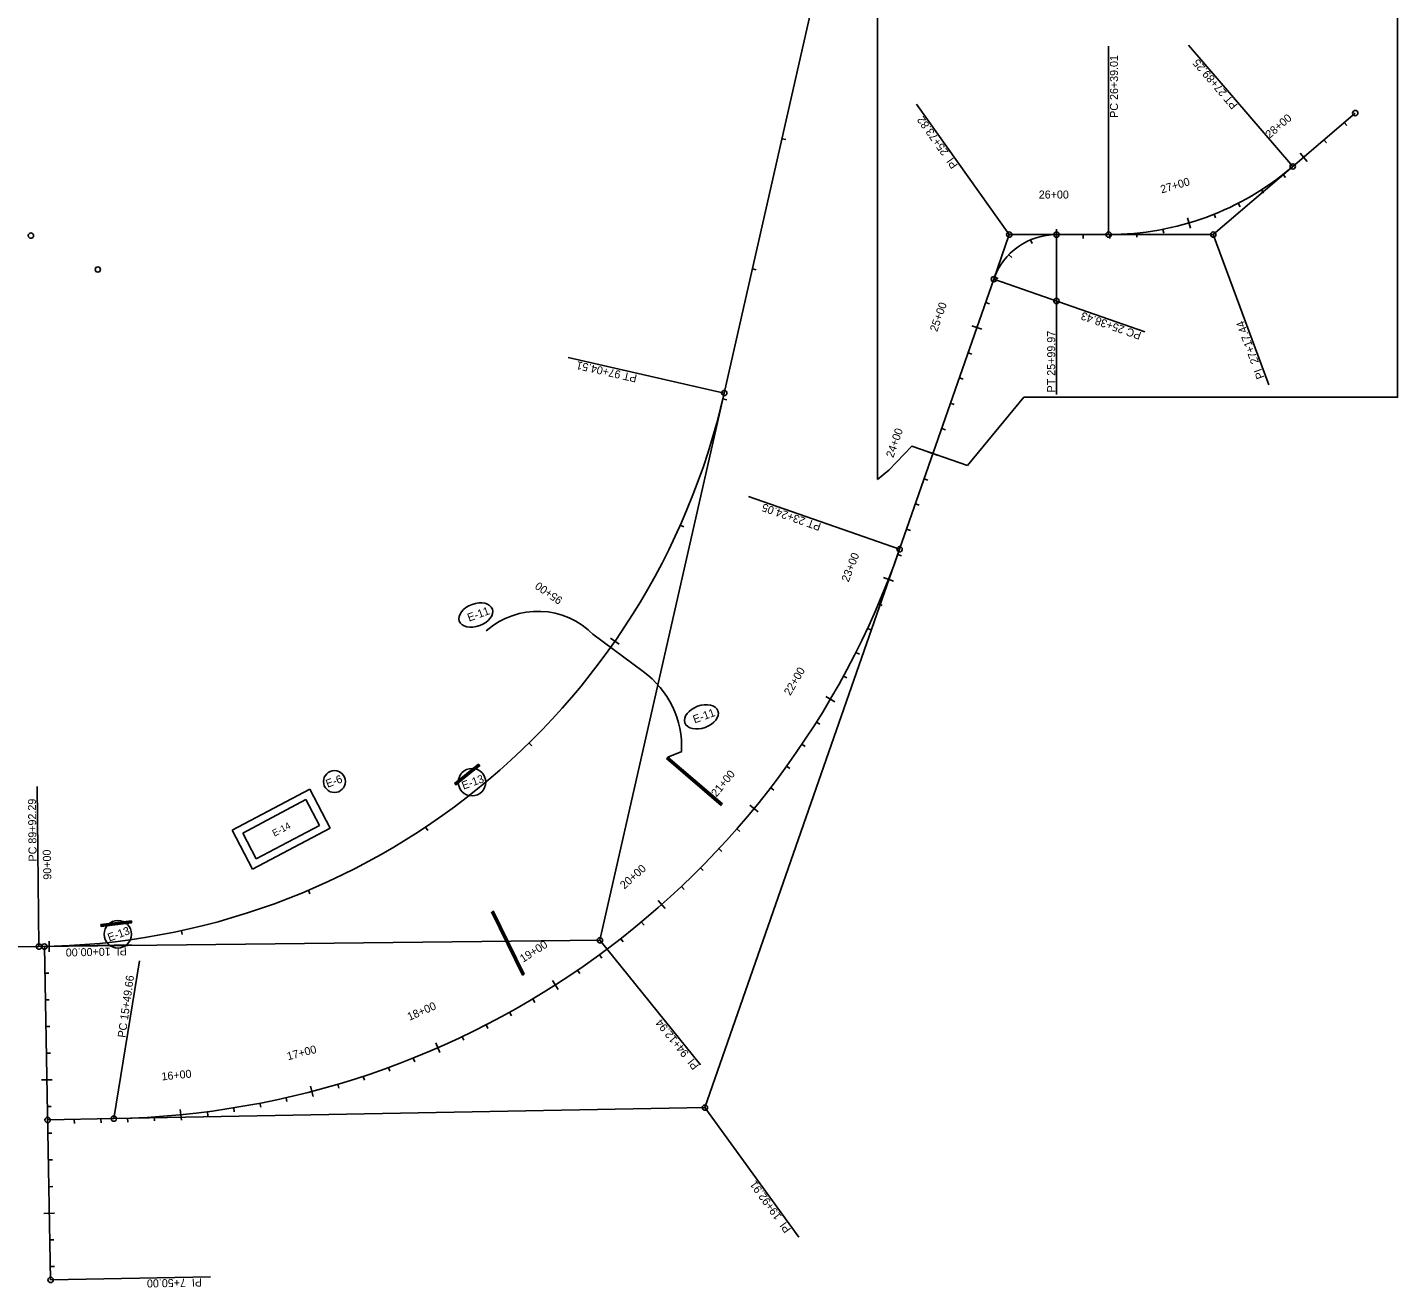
# Model space of a CAD drawing. Extents: x 1710760 to 1713003, y 548603 to 551142.
# Drawn here: x 1711724 to 1712752, y 548957 to 549901 of the extents above; entities that cross this region are included whole.
import ezdxf

# ---------------------------------------------------------------- set-up
doc = ezdxf.new("R2010")
doc.units = 0
for name, color, linetype in [('R_Erosion', 7, 'Continuous'), ('R_Erosion_STG 2', 7, 'Continuous'), ('R_Horz Alg', 7, 'Continuous'), ('R_Horz Alg Annot', 7, 'Continuous'), ('R_No Plot', 7, 'Continuous')]:
    doc.layers.add(name, color=color, linetype=linetype)

msp = doc.modelspace()

# ---------------------------------------------------------------- linework, layer by layer
at = {"layer": 'R_Erosion'}
for p, q in [((1712148.3, 549446.5), (1712186.1, 549418.7)), ((1712214.9, 549358.7), (1712204.5, 549354.4)), ((1712044.6, 549334.7), (1712062.6, 549349.2)), ((1712060.3, 549345.4), (1712060.5, 549347.5)), ((1712061.4, 549346.3), (1712061.6, 549348.4)), ((1712062.5, 549347.1), (1712062.7, 549349)), ((1712204.5, 549354.4), (1712203.5, 549353.3)), ((1712203.5, 549353.3), (1712244.6, 549318.1)), ((1712205.8, 549353.3), (1712203.6, 549353.2)), ((1712204.7, 549354.3), (1712204.4, 549354.2)), ((1712245.6, 549319.3), (1712204.5, 549354.4)), ((1712206.8, 549352.4), (1712204.7, 549352.3)), ((1712207.9, 549351.5), (1712205.8, 549351.3)), ((1712209, 549350.6), (1712206.9, 549350.4)), ((1712210.1, 549349.7), (1712207.9, 549349.5)), ((1712211.1, 549348.7), (1712209, 549348.6)), ((1712212.2, 549347.8), (1712210.1, 549347.7)), ((1712213.3, 549346.9), (1712211.2, 549346.7)), ((1712047, 549334.7), (1712047.2, 549336.9)), ((1712048.1, 549335.6), (1712048.4, 549337.7)), ((1712049.2, 549336.5), (1712049.5, 549338.6)), ((1712050.3, 549337.4), (1712050.6, 549339.5)), ((1712051.4, 549338.3), (1712051.7, 549340.4)), ((1712052.5, 549339.2), (1712052.8, 549341.3)), ((1712053.6, 549340.1), (1712053.9, 549342.2)), ((1712054.7, 549340.9), (1712055, 549343.1)), ((1712055.8, 549341.8), (1712056.1, 549343.9)), ((1712056.9, 549342.7), (1712057.2, 549344.8)), ((1712058, 549343.6), (1712058.3, 549345.7)), ((1712059.1, 549344.5), (1712059.4, 549346.6)), ((1712214.4, 549346), (1712212.2, 549345.8)), ((1712215.4, 549345.1), (1712213.3, 549344.9)), ((1712216.5, 549344.1), (1712214.4, 549344)), ((1712217.6, 549343.2), (1712215.5, 549343.1)), ((1712218.7, 549342.3), (1712216.5, 549342.1)), ((1712219.7, 549341.4), (1712217.6, 549341.2)), ((1712220.8, 549340.5), (1712218.7, 549340.3)), ((1712221.9, 549339.6), (1712219.8, 549339.4)), ((1712223, 549338.6), (1712220.8, 549338.5)), ((1712224, 549337.7), (1712221.9, 549337.5)), ((1712225.1, 549336.8), (1712223, 549336.6)), ((1711877.8, 549299.6), (1711936.1, 549330.4)), ((1711936.1, 549330.4), (1711951.4, 549301.2)), ((1712045, 549334.3), (1712045, 549335.1)), ((1712045.9, 549333.9), (1712046.1, 549336)), ((1712226.2, 549335.9), (1712224.1, 549335.7)), ((1712227.3, 549335), (1712225.1, 549334.8)), ((1712228.3, 549334), (1712226.2, 549333.9)), ((1712229.4, 549333.1), (1712227.3, 549333)), ((1712230.5, 549332.2), (1712228.4, 549332)), ((1712231.6, 549331.3), (1712229.4, 549331.1)), ((1712232.6, 549330.4), (1712230.5, 549330.2)), ((1712233.7, 549329.4), (1712231.6, 549329.3)), ((1712234.8, 549328.5), (1712232.7, 549328.4)), ((1712235.9, 549327.6), (1712233.7, 549327.4)), ((1712236.9, 549326.7), (1712234.8, 549326.5)), ((1711885.8, 549297.5), (1711933.2, 549322.6)), ((1711933.2, 549322.6), (1711943.4, 549303.2)), ((1712238, 549325.8), (1712235.9, 549325.6)), ((1712239.1, 549324.8), (1712237, 549324.7)), ((1712240.2, 549323.9), (1712238, 549323.8)), ((1712241.2, 549323), (1712239.1, 549322.8)), ((1712242.3, 549322.1), (1712240.2, 549321.9)), ((1712243.4, 549321.2), (1712241.3, 549321)), ((1712244.5, 549320.3), (1712242.3, 549320.1)), ((1712245.5, 549319.3), (1712243.4, 549319.2)), ((1712244.8, 549318.3), (1712244.5, 549318.2)), ((1711877.8, 549299.6), (1711893.1, 549270.3)), ((1711885.8, 549297.5), (1711896, 549278.2)), ((1711893.1, 549270.3), (1711951.4, 549301.2)), ((1711896, 549278.2), (1711943.4, 549303.2)), ((1712095.6, 549191), (1712072.2, 549238.5)), ((1712074.6, 549237), (1712072.6, 549237.7)), ((1712074, 549238.3), (1712072.7, 549238.7)), ((1712075.2, 549235.8), (1712073.2, 549236.4)), ((1712073.5, 549239.2), (1712096.9, 549191.7)), ((1712075.9, 549234.5), (1712073.8, 549235.2)), ((1712076.5, 549233.2), (1712074.5, 549233.9)), ((1711802.3, 549231.7), (1711779.5, 549228.9)), ((1711779.6, 549228.1), (1711780.2, 549229)), ((1711780.3, 549227.5), (1711781.6, 549229.1)), ((1711781.7, 549227.6), (1711783, 549229.3)), ((1711783.1, 549227.8), (1711784.4, 549229.5)), ((1711784.5, 549228), (1711785.8, 549229.7)), ((1711785.9, 549228.2), (1711787.2, 549229.8)), ((1711787.3, 549228.3), (1711788.6, 549230)), ((1711788.7, 549228.5), (1711790, 549230.2)), ((1711790.1, 549228.7), (1711791.4, 549230.3)), ((1711791.5, 549228.8), (1711792.8, 549230.5)), ((1711792.9, 549229), (1711794.2, 549230.7)), ((1711794.3, 549229.2), (1711795.7, 549230.9)), ((1711795.8, 549229.4), (1711797.1, 549231)), ((1711797.2, 549229.5), (1711798.5, 549231.2)), ((1711798.6, 549229.7), (1711799.9, 549231.4)), ((1711800, 549229.9), (1711801.3, 549231.6)), ((1711801.4, 549230.1), (1711802.3, 549231.3)), ((1712077.1, 549232), (1712075.1, 549232.6)), ((1712077.7, 549230.7), (1712075.7, 549231.4)), ((1712078.3, 549229.4), (1712076.3, 549230.1)), ((1712079, 549228.2), (1712077, 549228.8)), ((1712079.6, 549226.9), (1712077.6, 549227.6)), ((1712080.2, 549225.6), (1712078.2, 549226.3)), ((1712080.8, 549224.3), (1712078.8, 549225)), ((1712081.5, 549223.1), (1712079.5, 549223.8)), ((1712082.1, 549221.8), (1712080.1, 549222.5)), ((1712082.7, 549220.5), (1712080.7, 549221.2)), ((1712083.3, 549219.3), (1712081.3, 549220)), ((1712084, 549218), (1712082, 549218.7)), ((1712084.6, 549216.7), (1712082.6, 549217.4)), ((1712085.2, 549215.5), (1712083.2, 549216.1)), ((1712085.8, 549214.2), (1712083.8, 549214.9)), ((1712086.5, 549212.9), (1712084.5, 549213.6)), ((1712087.1, 549211.7), (1712085.1, 549212.3)), ((1712087.7, 549210.4), (1712085.7, 549211.1)), ((1712088.3, 549209.1), (1712086.3, 549209.8)), ((1712089, 549207.8), (1712087, 549208.5)), ((1712089.6, 549206.6), (1712087.6, 549207.3)), ((1712090.2, 549205.3), (1712088.2, 549206)), ((1712090.8, 549204), (1712088.8, 549204.7)), ((1712091.5, 549202.8), (1712089.5, 549203.5)), ((1712092.1, 549201.5), (1712090.1, 549202.2)), ((1712092.7, 549200.2), (1712090.7, 549200.9)), ((1712093.3, 549199), (1712091.3, 549199.6)), ((1712094, 549197.7), (1712092, 549198.4)), ((1712094.6, 549196.4), (1712092.6, 549197.1)), ((1712095.2, 549195.2), (1712093.2, 549195.8)), ((1712095.8, 549193.9), (1712093.8, 549194.6)), ((1712096.5, 549192.6), (1712094.5, 549193.3)), ((1712096.6, 549191.5), (1712095.1, 549192)), ((1712096.9, 549191.7), (1712095.6, 549191))]:
    msp.add_line(p, q, dxfattribs=at)
for points in [[(1712062.6, 549349.2), (1712063.5, 549348), (1712045.6, 549333.6), (1712044.6, 549334.7)], [(1711779.5, 549228.9), (1711779.7, 549227.4), (1711802.5, 549230.2), (1711802.3, 549231.7)]]:
    msp.add_lwpolyline(points, dxfattribs=at)
msp.add_circle((1711954.6, 549336.1), 8.26, dxfattribs=at)
for centre, radius, start, end in [((1712107.1, 549405.4), 58.3, 44.026, 131.674), ((1712143.9, 549361.5), 71, 357.7547, 53.5498)]:
    msp.add_arc(centre, radius, start, end, dxfattribs=at)
for centre in [(1712060.6, 549460.9), (1712229.7, 549384.6)]:
    msp.add_ellipse(centre, major_axis=(12.4, 4.5), ratio=0.638788, dxfattribs=at)
at = {"layer": 'R_Erosion_STG 2'}
for centre in [(1712057.7, 549335.6), (1711792.2, 549221.6)]:
    msp.add_circle(centre, 10.3, dxfattribs=at)
at = {"layer": 'R_Horz Alg'}
for p, q in [((1712246.8, 549627.3), (1712450.8, 550525.8)), ((1712673, 549797.1), (1712719.9, 549837.2)), ((1712495.9, 549746.1), (1712535, 549746.1)), ((1712378.3, 549510.2), (1712448.9, 549712.7)), ((1711391.8, 549208.5), (1711733, 549212.4)), ((1711741.8, 548962.5), (1711737.1, 549212.4)), ((1711739.5, 549082.4), (1711789.2, 549083.4))]:
    msp.add_line(p, q, dxfattribs=at)
for centre, radius, start, end in [((1712535, 549958.3), 212.2, 270, 310.5648), ((1712495.9, 549696.3), 49.8, 90, 160.7734), ((1711727, 549745.3), 533, 270.6428, 347.2066), ((1711777.2, 549719.9), 636.6, 271.0787, 340.7734)]:
    msp.add_arc(centre, radius, start, end, dxfattribs=at)
at = {"layer": 'R_Horz Alg Annot'}
for p, q in [((1712613.4, 549746.1), (1712673, 549797.1)), ((1712448.9, 549712.7), (1712460.5, 549746.1)), ((1712460.5, 549746.1), (1712495.9, 549746.1)), ((1712535, 549746.1), (1712613.4, 549746.1)), ((1712153.6, 549217.1), (1712246.8, 549627.3)), ((1712232.3, 549091.7), (1712378.3, 549510.2)), ((1711733, 549212.4), (1712153.6, 549217.1)), ((1711737.1, 549212.4), (1711802.4, 549213.6)), ((1711789.2, 549083.4), (1712232.3, 549091.7))]:
    msp.add_line(p, q, dxfattribs=at)
for points in [[(1712535, 549746.1), (1712535, 549887.4)], [(1712673, 549797.1), (1712594.9, 549888.2)], [(1712460.5, 549746.1), (1712391, 549843.9)], [(1712713.5, 549827.8), (1712711.5, 549830.1)], [(1712293, 549817.3), (1712290.1, 549817.9)], [(1712698.3, 549814.8), (1712696.3, 549817.1)], [(1712678.5, 549807.1), (1712683.7, 549801)], [(1712667.7, 549788.8), (1712665.8, 549791.2)], [(1712651.1, 549777.1), (1712649.5, 549779.6)], [(1712633.6, 549767), (1712632.2, 549769.7)], [(1712594, 549758.6), (1712596.3, 549750.9)], [(1712615.1, 549758.6), (1712614, 549761.3)], [(1712496, 549750.1), (1712496, 549742.1)], [(1712576.3, 549747.1), (1712575.7, 549750)], [(1712477.7, 549739.4), (1712476.5, 549742.1)], [(1712495.9, 549746.1), (1712495.9, 549626.1)], [(1712516, 549743.1), (1712516, 549746.1)], [(1712536, 549743.1), (1712536, 549746.1)], [(1712556.2, 549744.1), (1712555.9, 549747.1)], [(1712613.4, 549746.1), (1712655, 549633.5)], [(1712462.3, 549728.8), (1712460.1, 549730.9)], [(1712270.8, 549719.7), (1712267.9, 549720.4)], [(1712448.9, 549712.7), (1712562.2, 549673.1)], [(1712452.2, 549713.1), (1712449.4, 549714.1)], [(1712445.6, 549694.3), (1712442.8, 549695.3)], [(1712432.4, 549677.7), (1712440, 549675.1)], [(1712432.5, 549656.5), (1712429.6, 549657.5)], [(1712246.8, 549627.3), (1712129.8, 549653.9)], [(1712425.9, 549637.6), (1712423.1, 549638.6)], [(1712248.7, 549622.2), (1712245.8, 549622.9)], [(1712419.3, 549618.7), (1712416.5, 549619.7)], [(1712412.7, 549599.8), (1712409.9, 549600.8)], [(1712399.5, 549583.3), (1712407.1, 549580.6)], [(1712399.5, 549562.1), (1712396.7, 549563.1)], [(1712378.3, 549510.2), (1712265, 549549.8)], [(1712393, 549543.2), (1712390.1, 549544.2)], [(1712216.6, 549527.1), (1712213.8, 549528.3)], [(1712386.4, 549524.3), (1712383.5, 549525.3)], [(1712379.8, 549505.4), (1712376.9, 549506.4)], [(1712366.2, 549489.1), (1712373.7, 549486.2)], [(1712365.1, 549468), (1712362.4, 549469.2)], [(1712356.9, 549449.7), (1712354.2, 549450.9)], [(1712161.5, 549443.6), (1712168.1, 549439)], [(1712348.1, 549431.6), (1712345.5, 549432.9)], [(1712338.8, 549413.8), (1712336.2, 549415.2)], [(1712322.9, 549399.8), (1712329.8, 549395.8)], [(1712318.5, 549379.1), (1712315.9, 549380.7)], [(1712102.5, 549362.8), (1712100.4, 549365)], [(1712307.5, 549362.3), (1712305, 549364)], [(1712296, 549345.8), (1712293.6, 549347.6)], [(1711733, 549212.4), (1711731.7, 549332.3)], [(1712284, 549329.7), (1712281.6, 549331.5)], [(1712266.1, 549318.4), (1712272.3, 549313.3)], [(1712024.6, 549299.5), (1712022.9, 549302)], [(1712258.5, 549298.6), (1712256.2, 549300.6)], [(1712245, 549283.7), (1712242.8, 549285.8)], [(1712231.1, 549269.3), (1712229, 549271.4)], [(1711936.2, 549251.8), (1711935, 549254.6)], [(1712216.7, 549255.2), (1712214.7, 549257.4)], [(1712197.3, 549246.9), (1712202.6, 549240.9)], [(1711840.5, 549221.5), (1711839.8, 549224.4)], [(1712186.7, 549228.5), (1712184.8, 549230.8)], [(1711740.6, 549216.5), (1711740.8, 549208.5)], [(1712153.6, 549217.1), (1712229, 549123.7)], [(1712171, 549215.9), (1712169.2, 549218.3)], [(1712155, 549203.8), (1712153.2, 549206.2)], [(1711789.2, 549083.4), (1711808.5, 549201.7)], [(1712138.6, 549192.2), (1712136.9, 549194.7)], [(1711740.4, 549192.5), (1711737.4, 549192.4)], [(1712118.1, 549187), (1712122.4, 549180.2)], [(1711740.8, 549172.5), (1711737.8, 549172.4)], [(1712104.8, 549170.5), (1712103.2, 549173.1)], [(1712087.4, 549160.5), (1712085.9, 549163.1)], [(1711741.2, 549152.5), (1711738.2, 549152.4)], [(1712069.6, 549151), (1712068.3, 549153.7)], [(1712051.6, 549142.1), (1712050.3, 549144.8)], [(1711741.6, 549132.5), (1711738.6, 549132.4)], [(1712030.5, 549140.2), (1712033.7, 549132.9)], [(1711996, 549118.9), (1711995, 549121.7)], [(1712014.8, 549126), (1712013.7, 549128.8)], [(1711734.9, 549112.4), (1711742.9, 549112.5)], [(1711977, 549112.3), (1711976.1, 549115.1)], [(1711936.7, 549107.7), (1711938.7, 549100)], [(1711957.9, 549106.3), (1711957, 549109.2)], [(1711742.3, 549092.5), (1711739.3, 549092.4)], [(1711839, 549090.3), (1711839.8, 549082.3)], [(1711879.5, 549088.5), (1711879.1, 549091.5)], [(1711899.3, 549092), (1711898.7, 549095)], [(1711919, 549096.2), (1711918.3, 549099.1)], [(1712232.3, 549091.7), (1712302.7, 548994.5)], [(1711759.6, 549079.8), (1711759.5, 549082.8)], [(1711779.6, 549080.2), (1711779.5, 549083.2)], [(1711799.6, 549080.7), (1711799.5, 549083.7)], [(1711819.7, 549081.7), (1711819.5, 549084.7)], [(1711859.7, 549085.6), (1711859.3, 549088.6)], [(1711742.7, 549072.5), (1711739.7, 549072.4)], [(1711743.1, 549052.5), (1711740.1, 549052.4)], [(1711743.4, 549032.5), (1711740.4, 549032.4)], [(1711736.8, 549012.4), (1711744.8, 549012.5)], [(1711744.2, 548992.5), (1711741.2, 548992.5)], [(1711744.6, 548972.5), (1711741.6, 548972.5)], [(1711741.8, 548962.5), (1711861.7, 548964.7)]]:
    msp.add_lwpolyline(points, dxfattribs=at)
for centre in [(1712719.9, 549837.2), (1712673, 549797.1), (1712460.5, 549746.1), (1712495.9, 549746.1), (1712535, 549746.1), (1712613.4, 549746.1), (1711727, 549745.3), (1711777.2, 549719.9), (1712448.9, 549712.7), (1712495.9, 549696.3), (1712246.8, 549627.3), (1712378.3, 549510.2), (1711733, 549212.4), (1711733, 549212.4), (1711737.1, 549212.4), (1712153.6, 549217.1), (1712232.3, 549091.7), (1711739.5, 549082.4), (1711789.2, 549083.4), (1711741.8, 548962.5)]:
    msp.add_circle(centre, 2, dxfattribs=at)
at = {"layer": 'R_No Plot'}
msp.add_line((1712429.3, 549572.9), (1712471.5, 549624.2), dxfattribs=at)
for points in [[(1712635.8, 549942.6), (1712361.6, 549942.6), (1712361.6, 549562.6)], [(1712471.5, 549624.2), (1712751.6, 549624.2), (1712751.6, 549942.6), (1712636.3, 549942.6)], [(1712361.6, 549562.6), (1712370.3, 549569.5), (1712387.4, 549587.5), (1712429.3, 549572.9)]]:
    msp.add_lwpolyline(points, dxfattribs=at)

# ---------------------------------------------------------------- texts
at = {"layer": 'R_Erosion'}
for s, height, rotation, p in [('E-11', 6, 20, (1712055.5, 549455.9)), ('E-11', 6, 20, (1712224.6, 549379.6)), ('E-6 ', 6, 20, (1711949.4, 549331.4)), ('E-14', 5.08, 27.831, (1711909.6, 549294.7))]:
    msp.add_text(s, height=height, rotation=rotation, dxfattribs=at).set_placement(p)
at = {"layer": 'R_Erosion_STG 2'}
for p in [(1712051.3, 549330), (1711785.8, 549216.1)]:
    msp.add_text('E-13', height=6, rotation=20, dxfattribs=at).set_placement(p)
at = {"layer": 'R_Horz Alg Annot'}
for s, rotation, p in [('PC 26+39.01', 90, (1712542, 549833.6)), ('PT 27+89.25', 130.5648, (1712632.1, 549843.3)), ('PI  25+73.82', 125.3867, (1712422.3, 549798.2)), ('28+00', 40.5648, (1712655.7, 549817.9)), ('27+00', 16.4663, (1712574.8, 549776.9)), ('25+00', 70.7734, (1712406.4, 549672.8)), ('PC 25+38.43', 160.7734, (1712560, 549672.8)), ('PI  27+17.44', 110.2824, (1712651.9, 549639.1)), ('PT 25+99.97', 90, (1712494.9, 549627.8)), ('PT 97+04.51', 167.2066, (1712181.8, 549641)), ('24+00', 70.7734, (1712373.5, 549578.4)), ('PT 23+24.05', 160.7734, (1712319.9, 549529.5)), ('23+00', 68.6088, (1712340, 549485.2)), ('95+00', 145.2214, (1712126.2, 549473.3)), ('22+00', 59.6088, (1712296.3, 549400.1)), ('21+00', 50.6088, (1712241, 549324.1)), ('PC 89+92.29', 90.6428, (1711731.3, 549276.2)), ('90+00', 91.4714, (1711742.4, 549262.6)), ('20+00', 41.6088, (1712171.9, 549255.1)), ('19+00', 32.6088, (1712096, 549200.2)), ('PI  10+00.00', 181.0787, (1711798.8, 549211.8)), ('PC 15+49.66', 82.0728, (1711797.9, 549143.8)), ('18+00', 23.6088, (1712010.8, 549156.7)), ('PI  94+12.94', 128.9247, (1712228.2, 549123.1)), ('17+00', 14.6088, (1711919.8, 549127.1)), ('16+00', 5.6088, (1711825.2, 549112)), ('PI  19+92.91', 125.926, (1712297.2, 549000.5)), ('PI  7+50.00', 181.0787, (1711855.2, 548963.6))]:
    msp.add_text(s, height=6, rotation=rotation, dxfattribs=at).set_placement(p)
msp.add_text('26+00', height=6, dxfattribs=at).set_placement((1712482.6, 549773.1))

doc.saveas('drawing.dxf')
